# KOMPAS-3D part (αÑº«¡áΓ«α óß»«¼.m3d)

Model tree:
1. Эскиз:1
2. Операция выдавливания:1
     Толщина стенки 1 = 2; Толщина стенки 2 = 8; Расстояние 1 = 1
3. Эскиз:3
4. Операция выдавливания:2
     Толщина стенки 1 = 2; Толщина стенки 2 = 6; Расстояние 1 = 5.5
5. Эскиз:4
6. Операция выдавливания:3
     Толщина стенки 1 = 2; Толщина стенки 2 = 6; Расстояние 1 = 1
7. Эскиз:5
8. Эскиз:6
9. Операция выдавливания:4
     Толщина стенки 1 = 2; Толщина стенки 2 = 2.5; Расстояние 1 = 50
10. Эскиз:7
11. Вырезать элемент выдавливания:1
     Толщина стенки 2 = 1.5; Расстояние 1 = 40
12. Эскиз:8
13. Операция выдавливания:5
     Толщина стенки 1 = 2; Толщина стенки 2 = 2.5; Расстояние 1 = 50
14. Эскиз:9
15. Вырезать элемент выдавливания:2
     Толщина стенки 2 = 1.5; Расстояние 1 = 40
16. Эскиз:10
17. Операция выдавливания:6
     Толщина стенки 1 = 2; Толщина стенки 2 = 2.5; Расстояние 1 = 10
18. Эскиз:11
19. Операция выдавливания:7
     Толщина стенки 1 = 2; Толщина стенки 2 = 6; Расстояние 1 = 1
20. Эскиз:12
21. Операция выдавливания:8
     Толщина стенки 1 = 2; Толщина стенки 2 = 6; Расстояние 1 = 5.5
22. Эскиз:13
23. Операция выдавливания:9
     Толщина стенки 1 = 2; Толщина стенки 2 = 8; Расстояние 1 = 1
24. Эскиз:14
25. Вырезать элемент выдавливания:3
     Толщина стенки 2 = 1.5; Расстояние 1 = 23
26. Эскиз:15
27. Вырезать элемент выдавливания:4
     Толщина стенки 2 = 1.5; Расстояние 1 = 1
